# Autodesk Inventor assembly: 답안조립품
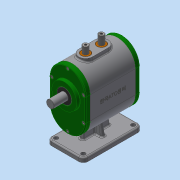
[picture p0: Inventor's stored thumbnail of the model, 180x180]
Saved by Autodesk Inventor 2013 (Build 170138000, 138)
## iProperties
Created: 2018-10
Part Number: 답안조립품
Document SubType Name: Assembly
Designer: Administrator
Author: Administrator
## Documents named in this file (15)
- C:\Users\Administrator\Desktop\381007V1028\381007V1028\답안조립품.iam
- C:\Users\Administrator\Desktop\381007V1028\381007V1028\본체.ipt
- C:\Users\Administrator\Desktop\381007V1028\381007V1028\가변스프링.ipt
- C:\Users\Administrator\Desktop\381007V1028\381007V1028\뒤커버.ipt
- C:\Users\Administrator\Desktop\381007V1028\381007V1028\메인축.ipt
- C:\Users\Administrator\Desktop\381007V1028\381007V1028\베어링 608.ipt
- C:\Users\Administrator\Desktop\381007V1028\381007V1028\베어링 6003.ipt
- C:\Users\Administrator\Desktop\381007V1028\381007V1028\볼트 M4.ipt
- C:\Users\Administrator\Desktop\381007V1028\381007V1028\부시.ipt
- C:\Users\Administrator\Desktop\381007V1028\381007V1028\서브축.ipt
- C:\Users\Administrator\Desktop\381007V1028\381007V1028\슬라이더.ipt
- C:\Users\Administrator\Desktop\381007V1028\381007V1028\앞커버.ipt
- C:\Users\Administrator\Desktop\381007V1028\381007V1028\오일실 8 22 7.ipt
- C:\Users\Administrator\Desktop\381007V1028\381007V1028\오일실 17 32 8.ipt
- C:\Users\Administrator\Desktop\381007V1028\381007V1028\가변스프링2.ipt
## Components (2 placed, 2 different names)
1. 가변스프링:1
2. 가변스프링2:1
